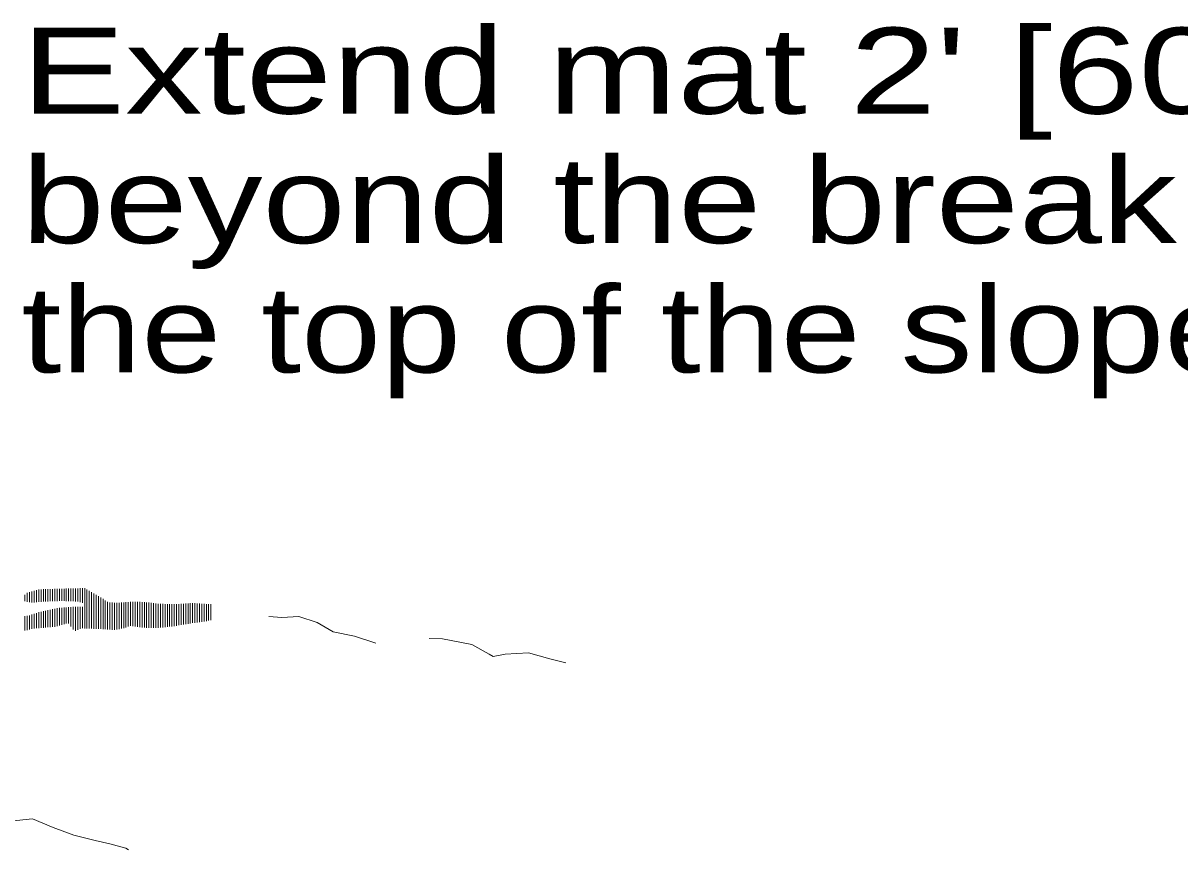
# Model space of a CAD drawing. Extents: x 1083.1 to 1117.1, y 719.4 to 741.4.
# Drawn here: x 1094.725 to 1096.824, y 723.5 to 724.999 of the extents above; entities that cross this region are included whole.
import ezdxf

# ---------------------------------------------------------------- set-up
doc = ezdxf.new("R2010")
doc.units = 0
doc.header["$LTSCALE"] = 0.062
doc.layers.add('1', color=7, linetype='Continuous', lineweight=13)

msp = doc.modelspace()

# ---------------------------------------------------------------- linework, layer by layer
at = {"layer": '1'}
for p, q in [((1094.72867, 723.95108), (1094.72867, 723.96242)), ((1094.73283, 723.95008), (1094.73283, 723.96642)), ((1094.737, 723.949), (1094.737, 723.96758)), ((1094.74117, 723.94842), (1094.74117, 723.96875)), ((1094.74533, 723.94892), (1094.74533, 723.96992)), ((1094.7495, 723.94925), (1094.7495, 723.97108)), ((1094.75367, 723.94958), (1094.75367, 723.97225)), ((1094.75783, 723.95), (1094.75783, 723.97242)), ((1094.762, 723.95042), (1094.762, 723.97258)), ((1094.76617, 723.95058), (1094.76617, 723.97275)), ((1094.77033, 723.95075), (1094.77033, 723.97283)), ((1094.7745, 723.95092), (1094.7745, 723.97292)), ((1094.77867, 723.951), (1094.77867, 723.97308)), ((1094.78283, 723.95117), (1094.78283, 723.97317)), ((1094.787, 723.95133), (1094.787, 723.97325)), ((1094.79117, 723.9515), (1094.79117, 723.97342)), ((1094.79533, 723.95142), (1094.79533, 723.9735)), ((1094.7995, 723.95142), (1094.7995, 723.97358)), ((1094.80367, 723.95125), (1094.80367, 723.97375)), ((1094.80783, 723.95108), (1094.80783, 723.97383)), ((1094.812, 723.95108), (1094.812, 723.97392)), ((1094.81617, 723.95092), (1094.81617, 723.97408)), ((1094.82033, 723.95075), (1094.82033, 723.97425)), ((1094.8245, 723.95075), (1094.8245, 723.97433)), ((1094.82867, 723.9495), (1094.82867, 723.97442)), ((1094.83283, 723.948), (1094.83283, 723.97458)), ((1094.837, 723.90167), (1094.837, 723.97475)), ((1094.84117, 723.90158), (1094.84117, 723.9725)), ((1094.84533, 723.9015), (1094.84533, 723.97)), ((1094.8495, 723.90133), (1094.8495, 723.96758)), ((1094.85367, 723.90117), (1094.85367, 723.96508)), ((1094.85783, 723.90108), (1094.85783, 723.96258)), ((1094.862, 723.90092), (1094.862, 723.96008)), ((1094.86617, 723.90067), (1094.86617, 723.95758)), ((1094.87025, 723.90042), (1094.87025, 723.95508)), ((1094.76617, 723.90333), (1094.76617, 723.93375)), ((1094.77033, 723.90367), (1094.77033, 723.93458)), ((1094.7745, 723.904), (1094.7745, 723.93542)), ((1094.77867, 723.90433), (1094.77867, 723.93633)), ((1094.78283, 723.90467), (1094.78283, 723.93725)), ((1094.787, 723.90575), (1094.787, 723.93808)), ((1094.79117, 723.907), (1094.79117, 723.93875)), ((1094.79533, 723.90825), (1094.79533, 723.93908)), ((1094.7995, 723.9095), (1094.7995, 723.93942)), ((1094.80367, 723.91067), (1094.80367, 723.93975)), ((1094.80783, 723.91083), (1094.80783, 723.94008)), ((1094.812, 723.90492), (1094.812, 723.94042)), ((1094.81617, 723.89967), (1094.81617, 723.94067)), ((1094.82033, 723.89717), (1094.82033, 723.94075)), ((1094.8245, 723.89883), (1094.8245, 723.94075)), ((1094.82867, 723.90067), (1094.82867, 723.94075)), ((1094.83283, 723.90183), (1094.83283, 723.94075)), ((1094.87442, 723.90017), (1094.87442, 723.95258)), ((1094.87858, 723.89983), (1094.87858, 723.94992)), ((1094.88275, 723.89967), (1094.88275, 723.94875)), ((1094.88692, 723.89933), (1094.88692, 723.9485)), ((1094.89108, 723.89917), (1094.89108, 723.94825)), ((1094.89525, 723.89983), (1094.89525, 723.94808)), ((1094.89942, 723.9005), (1094.89942, 723.94808)), ((1094.90358, 723.90125), (1094.90358, 723.94842)), ((1094.90775, 723.902), (1094.90775, 723.94875)), ((1094.91192, 723.90325), (1094.91192, 723.949)), ((1094.91608, 723.90483), (1094.91608, 723.94925)), ((1094.92025, 723.90617), (1094.92025, 723.94958)), ((1094.92442, 723.90558), (1094.92442, 723.94983)), ((1094.92858, 723.905), (1094.92858, 723.95008)), ((1094.93275, 723.90433), (1094.93275, 723.94975)), ((1094.93692, 723.90383), (1094.93692, 723.94958)), ((1094.94108, 723.90333), (1094.94108, 723.94925)), ((1094.94525, 723.90317), (1094.94525, 723.94908)), ((1094.94942, 723.903), (1094.94942, 723.94875)), ((1094.95358, 723.90283), (1094.95358, 723.9485)), ((1094.95775, 723.90275), (1094.95775, 723.94825)), ((1094.96192, 723.90267), (1094.96192, 723.94767)), ((1094.96608, 723.9025), (1094.96608, 723.94692)), ((1094.97025, 723.90267), (1094.97025, 723.94625)), ((1094.97442, 723.90308), (1094.97442, 723.94608)), ((1094.97858, 723.9035), (1094.97858, 723.946)), ((1094.98275, 723.904), (1094.98275, 723.94592)), ((1094.98692, 723.90433), (1094.98692, 723.94575)), ((1094.99108, 723.90483), (1094.99108, 723.94567)), ((1094.99525, 723.90533), (1094.99525, 723.94558)), ((1094.99942, 723.90583), (1094.99942, 723.94542)), ((1095.00358, 723.9065), (1095.00358, 723.94558)), ((1095.00775, 723.90725), (1095.00775, 723.94592)), ((1095.01192, 723.908), (1095.01192, 723.94617)), ((1095.01608, 723.90867), (1095.01608, 723.94642)), ((1095.02025, 723.90933), (1095.02025, 723.94675)), ((1095.02442, 723.91008), (1095.02442, 723.94708)), ((1095.02858, 723.91083), (1095.02858, 723.94733)), ((1095.03275, 723.9115), (1095.03275, 723.94742)), ((1095.03692, 723.912), (1095.03692, 723.94717)), ((1095.04108, 723.9125), (1095.04108, 723.94692)), ((1095.04517, 723.913), (1095.04517, 723.94667)), ((1095.04933, 723.9135), (1095.04933, 723.94642)), ((1095.0535, 723.91408), (1095.0535, 723.94617)), ((1095.05767, 723.915), (1095.05767, 723.94592)), ((1095.06183, 723.91583), (1095.06183, 723.94567)), ((1095.066, 723.91675), (1095.066, 723.94558)), ((1094.72867, 723.89767), (1094.72867, 723.92408)), ((1094.73283, 723.89867), (1094.73283, 723.92433)), ((1094.737, 723.89967), (1094.737, 723.92517)), ((1094.74117, 723.90067), (1094.74117, 723.92667)), ((1094.74533, 723.90158), (1094.74533, 723.928)), ((1094.7495, 723.902), (1094.7495, 723.9295)), ((1094.75367, 723.90233), (1094.75367, 723.93083)), ((1094.75783, 723.90267), (1094.75783, 723.93192)), ((1094.762, 723.903), (1094.762, 723.93275))]:
    msp.add_line(p, q, dxfattribs=at)
for points in [[(1095.365, 723.875), (1095.32625, 723.88783), (1095.2875, 723.89567), (1095.25842, 723.9125), (1095.22575, 723.92342), (1095.19433, 723.92133), (1095.17133, 723.92317)], [(1095.70975, 723.8395), (1095.68075, 723.84633), (1095.64192, 723.85717), (1095.59958, 723.855), (1095.57792, 723.85092), (1095.57067, 723.85483), (1095.53917, 723.87267), (1095.48583, 723.8825), (1095.46167, 723.88342)], [(1094.64558, 723.56383), (1094.66258, 723.55692), (1094.69283, 723.551), (1094.71333, 723.55317), (1094.74233, 723.55625), (1094.77992, 723.54042), (1094.8175, 723.52658), (1094.85617, 723.51675), (1094.88275, 723.51083), (1094.91183, 723.503), (1094.91675, 723.5)]]:
    msp.add_lwpolyline(points, dxfattribs=at)

# ---------------------------------------------------------------- texts
for s, width, p in [("Extend mat 2' [600]", 1.35, (1094.72225, 724.83517)), ('beyond the break at', 1.3, (1094.72225, 724.6005)), ('the top of the slope.', 1.25, (1094.72225, 724.36583))]:
    msp.add_text(s, height=0.156, dxfattribs=dict(at, width=width)).set_placement(p)

doc.saveas('drawing.dxf')
